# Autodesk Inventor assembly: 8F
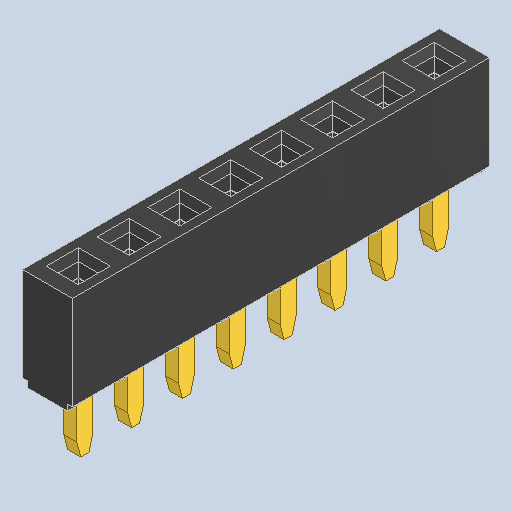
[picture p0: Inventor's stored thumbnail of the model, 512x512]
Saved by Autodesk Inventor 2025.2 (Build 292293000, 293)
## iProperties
Created: 2025-04
Part Number: 8F
Description: PART--DESC
Document SubType Name: Assembly
Designer: BennF
Author: BennF
Revision Number: NONE
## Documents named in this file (3)
- C:\Users\BennF\Nextcloud\Benutzer\CNC JarBeRi\existing parts\Electronics\RepRap A4988 Shied (USE WITHOUT ARDUINO)\reprap-a4988-1.snapshot.1\RepRap\RepRap\8F_1.iam
- C:\Users\BennF\Nextcloud\Benutzer\CNC JarBeRi\existing parts\Electronics\RepRap A4988 Shied (USE WITHOUT ARDUINO)\reprap-a4988-1.snapshot.1\RepRap\RepRap\8F Geometry.ipt
- C:\Users\BennF\Nextcloud\Benutzer\CNC JarBeRi\existing parts\Electronics\RepRap A4988 Shied (USE WITHOUT ARDUINO)\reprap-a4988-1.snapshot.1\RepRap\RepRap\Pin3.ipt
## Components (2 placed, 2 different names)
1. 8F Geometry
2. Pin3
